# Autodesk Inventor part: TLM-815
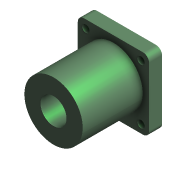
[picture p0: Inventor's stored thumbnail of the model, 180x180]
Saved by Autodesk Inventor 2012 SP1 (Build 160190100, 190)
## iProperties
Shininess: 25.0
Length Units: 11269
Angle Units: 11279
Time Units: 11290
Mass Units: 11283
Length Display Precision: 3
Angle Display Precision: 2
Compacted: True
Created: 2000-06
Part Number: TLM-815
Material: Aluminum
Description: SUPPER BALL BUSHING SINGLE1.0" SHAFT
Vendor: REID TOOL
Document SubType Name: Modeling
Designer: Ron
Density: 1 g/cm^3
Density: 0.0
Volumn: 0.0
Area: 0.0
PropertySet Name: Model Information
Control State: 0
Master: False
Checked Out: False
Author: Ron
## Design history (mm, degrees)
node "Extrusion1" dims "d2" = 12.7, "d3" = 0
  sketch "Sketch1"
    geometry: L1 (34.925, 34.925)-(-34.925, 34.925); L2 (-34.925, 34.925)-(-34.925, -34.925); L3 (-34.925, -34.925)-(34.925, -34.925); L4 (34.925, -34.925)-(34.925, 34.925); C1 r 34.925 at (0, 0); C2 r 12.713 at (0, 0); 1 further point
    constraints: 8 end point, 4 tangent, 2 centre point, 2 coincident, 2 parallel, 1 horizontal, 1 perpendicular
    dimensions: "d0" = 69.85 diameter of C1; "d1" = 25.4254 diameter of C2
node "Extrusion2" dims "d5" = 71.374, "d6" = 0
  sketch "Sketch2"
    geometry: C1 r 12.713 at (0, 0) reference; C2 r 28.575 at (0, 0)
    constraints: 1 centre point, 1 coincident
    dimensions: "d4" = 57.15 diameter of C2
node "Hole1" dims "d8" = 7.112, "d9" = 4, "d10" = 2, "d11" = 60 deg, "d12" = 8, "d13" = 118 deg
  sketch "Sketch3"
    geometry: L1 (-34.925, 34.925)-(34.925, 34.925) reference; L2 (-34.925, -34.925)-(-34.925, 34.925) reference; L3 (34.925, -34.925)-(-34.925, -34.925) reference; L4 (34.925, 34.925)-(34.925, -34.925) reference; L5 (-26.987, 26.988)-(26.988, 26.987); L6 (26.988, 26.987)-(26.987, -26.988); L7 (26.987, -26.988)-(-26.988, -26.988); L8 (-26.988, -26.988)-(-26.987, 26.988); 4 further points
    constraints: 8 end point, 4 coincident, 3 other
    dimensions: "d7" = 53.975 distance of L5.start L5.end
node "Fillet1" dims "d14" = 6
body "Solid1"
